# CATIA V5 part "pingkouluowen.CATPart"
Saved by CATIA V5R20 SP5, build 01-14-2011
Part number: Part1
Material "Red Carpet": density 750 kg/m3
Bounding box of the stored display mesh (mm): x -15.309 to 15.309, y -15.302 to 15.304, z -1 to 20
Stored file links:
  E:\180522132\3.8垫片\Part1.CATPart
  C:\Program Files\Dassault Systemes\B20\intel_a\startup\materials\Catalog.CATMaterial
  C:\Program Files\Dassault Systemes\B20\intel_a\startup\materials\red_carpet.jpg
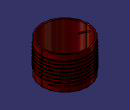
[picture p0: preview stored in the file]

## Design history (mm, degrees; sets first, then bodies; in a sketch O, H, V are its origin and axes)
Body1 (main body)
  Sketch1 on xy-plane, origin (0, 0, 0), H (1, 0, 0), V (0, 1, 0)
    circle A1 centre (0, 0) radius 15
    radius A1 = 15
  Pad1: profile Sketch1, direction (0, 0, 1), length 20, opposite side length 1, thin wall 1
  Plane1: type Offset, RefPlane xy-plane, Offset 2
  Sketch2 on Plane1, origin (0, 0, 2), H (1, 0, 0), V (0, 1, 0)
    point P1 (15, 0)
    distance P1 O = 15
    coincidence: P1 H
  Helix1: Direction Z axis, RefPoint Sketch2, Pitch 2, Height 15, TaperAngle 0
  Point1: type OnCurve, Support Helix1, RefPoint Sketch2, Length 5
  Line1: type PtDir, Direction (1, 0, 0), RefPoint Sketch2, Start 0, End -6
  Connect1: Curve1 Line1, Point1 vertex of Line1, Tension1 1, Curve2 Helix1, Point2 Point1, Tension2 1
  Line2: type PtDir, RefPoint vertex of Helix1, Direction (1, 0, 0), Start 0, End 6
  Point2: type OnCurve, Support Connect1, RefPoint vertex of Helix1, Length -4.247
  Connect2: Curve1 Connect1, Point1 Point2, Tension1 1, Curve2 Line2, Point2 vertex of Line2, Tension2 1
  Plane2: type Normal, Curve Connect2, RefPoint Point1
  Sketch3 on Plane2, origin (-0.0146, 0.0422, 0.0009), H (-0.945, -0.3271, 0), V (0.0069, -0.02, 0.9998)
    circle A1 centre (-14.9829, 2.1116) radius 0.3265
  Rib1: profile Sketch3, centre curve Connect2
Body2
